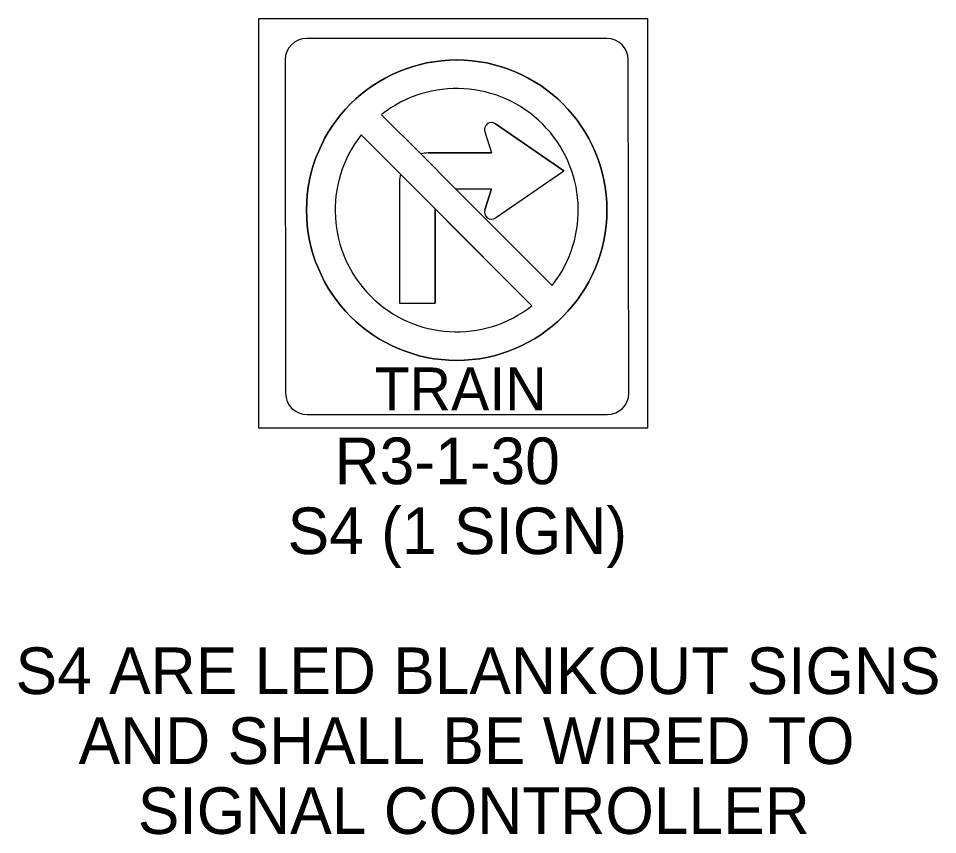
# Model space of a CAD drawing. Extents: x -32.9 to 34, y 0 to 22.3.
# Drawn here: x -4.169 to -1.408, y 7.743 to 10.193 of the extents above; entities that cross this region are included whole.
import ezdxf

# ---------------------------------------------------------------- set-up
doc = ezdxf.new("R2010")
doc.units = 0
doc.layers.add('PV_P_Curb', color=7, linetype='Continuous')
doc.layers.add('PV_P_Saw_Cut_Line', color=7, linetype='Continuous')

msp = doc.modelspace()

# ---------------------------------------------------------------- linework, layer by layer
at = {"layer": 'PV_P_Curb'}
msp.add_line((-3.1391, 9.843), (-2.6264, 9.3303), dxfattribs=at)
for points in [[(-2.9605, 9.7859), (-3.0784, 9.9037)], [(-3.1391, 9.843), (-3.0212, 9.7251)], [(-2.5657, 9.391), (-2.8561, 9.6814), (-2.9605, 9.7859)], [(-3.0212, 9.7251), (-2.9168, 9.6207), (-2.6264, 9.3303)]]:
    msp.add_lwpolyline(points, dxfattribs=at)
msp.add_circle((-2.8524, 9.617), 0.451, dxfattribs=at)
for radius, start, end in [(0.451, 0, 180), (0.3651, 321.7563, 128.2437), (0.3651, 321.7563, 128.2437), (0.3651, 141.7563, 308.2437), (0.3651, 141.7563, 308.2437), (0.451, 180, 0)]:
    msp.add_arc((-2.8524, 9.617), radius, start, end, dxfattribs=at)
at = {"layer": 'PV_P_Saw_Cut_Line'}
for p, q in [((-2.7355, 9.8763), (-2.5303, 9.7351)), ((-2.7682, 9.8522), (-2.7484, 9.7888)), ((-2.9383, 9.7888), (-2.7484, 9.7888)), ((-2.7355, 9.5939), (-2.5303, 9.7351)), ((-3.0242, 9.7029), (-3.0242, 9.3378)), ((-2.8561, 9.6814), (-2.7484, 9.6814)), ((-2.7682, 9.618), (-2.7484, 9.6814)), ((-2.9168, 9.6207), (-2.9168, 9.3378)), ((-3.0242, 9.3378), (-2.9168, 9.3378))]:
    msp.add_line(p, q, dxfattribs=at)
msp.add_lwpolyline([(-3.4465, 10.1927), (-2.2793, 10.1927), (-2.2793, 8.9625), (-3.4465, 8.9625)], close=True, dxfattribs=at)
for points in [[(-2.4014, 10.1324), (-3.3033, 10.1324)], [(-3.3678, 10.068), (-3.3663, 9.0677)], [(-2.3356, 9.0677), (-2.337, 10.068)], [(-2.7355, 9.5939), (-2.5303, 9.7351), (-2.7355, 9.8763)], [(-2.7682, 9.8522), (-2.7484, 9.7888), (-2.9383, 9.7888)], [(-2.9605, 9.7859), (-2.8561, 9.6814), (-2.7484, 9.6814), (-2.7682, 9.618)], [(-2.9168, 9.6207), (-3.0212, 9.7251)], [(-3.0242, 9.7029), (-3.0242, 9.3378), (-2.9168, 9.3378), (-2.9168, 9.6207)], [(-3.3019, 9.0033), (-2.4, 9.0033)]]:
    msp.add_lwpolyline(points, dxfattribs=at)
for centre, radius, start, end in [((-3.3033, 10.068), 0.0644, 90, 180), ((-2.4014, 10.068), 0.0644, 0, 90), ((-2.7477, 9.8586), 0.0215, 55.4837, 197.3618), ((-2.7477, 9.8586), 0.0215, 55.4837, 197.3618), ((-2.9383, 9.7029), 0.0859, 90, 105), ((-2.9383, 9.7029), 0.0859, 90, 105), ((-2.9383, 9.7029), 0.0859, 165, 180), ((-2.9383, 9.7029), 0.0859, 165, 180), ((-2.7477, 9.6116), 0.0215, 162.6382, 304.5163), ((-2.7477, 9.6116), 0.0215, 162.6382, 304.5163), ((-3.3019, 9.0677), 0.0644, 180, 270), ((-2.4, 9.0677), 0.0644, 270, 0)]:
    msp.add_arc(centre, radius, start, end, dxfattribs=at)

# ---------------------------------------------------------------- texts
for s, height, p in [('TRAIN', 0.12885, (-3.0991, 9.0159)), ('R3-1-30', 0.14, (-3.219, 8.7945)), ('S4 (1 SIGN) ', 0.14, (-3.3603, 8.5845)), ('S4 ARE LED BLANKOUT SIGNS', 0.14, (-4.1773, 8.1645)), ('AND SHALL BE WIRED TO ', 0.14, (-3.988, 7.9545)), ('SIGNAL CONTROLLER', 0.14, (-3.8102, 7.7445))]:
    msp.add_text(s, height=height, dxfattribs=at).set_placement(p)

doc.saveas('drawing.dxf')
